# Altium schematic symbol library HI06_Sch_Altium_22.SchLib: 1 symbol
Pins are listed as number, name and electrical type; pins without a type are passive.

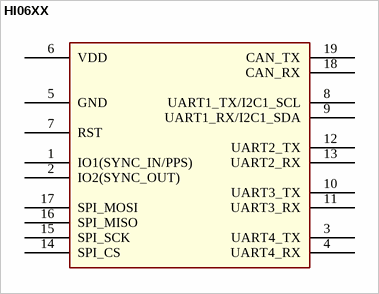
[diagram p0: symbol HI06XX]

## HI06XX
designator U?
pins: 1 IO1(SYNC_IN/PPS), 2 IO2(SYNC_OUT), 3 UART4_TX, 4 UART4_RX, 5 GND, 6 VDD, 7 RST, 8 UART1_TX/I2C1_SCL, 9 UART1_RX/I2C1_SDA, 10 UART3_TX, 11 UART3_RX, 12 UART2_TX, 13 UART2_RX, 14 SPI_CS, 15 SPI_SCK, 16 SPI_MISO, 17 SPI_MOSI (power), 18 CAN_RX (power), 19 CAN_TX (power)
